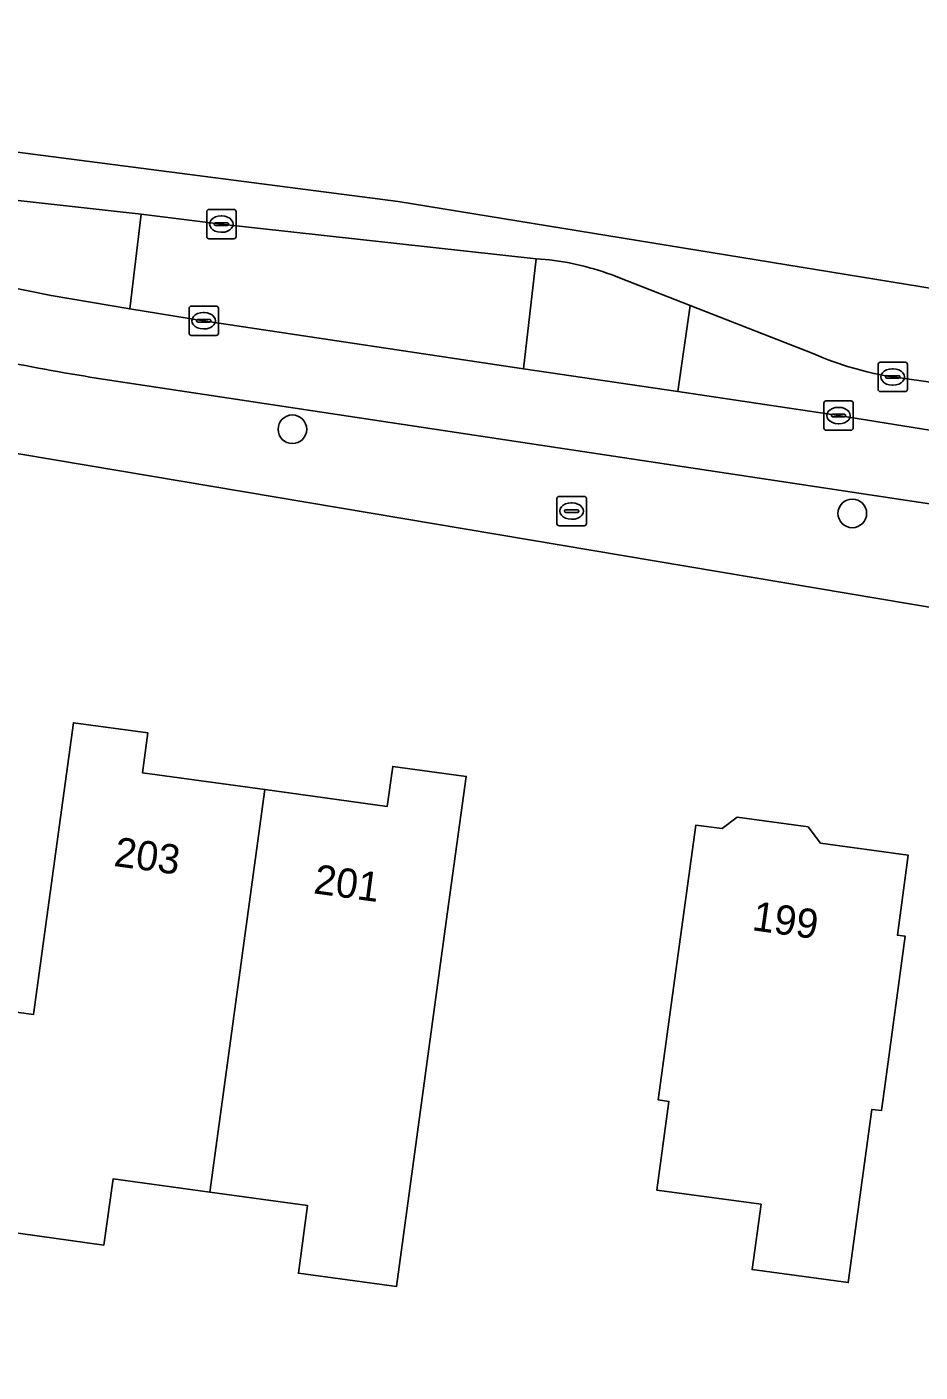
# Model space of a CAD drawing. Extents: x 161483 to 162250, y 379484 to 380833.
# Drawn here: x 161752.71 to 161783.16, y 380783.22 to 380829.09 of the extents above; entities that cross this region are included whole.
import ezdxf

# ---------------------------------------------------------------- set-up
doc = ezdxf.new("R2010")
doc.units = 0
for name, color, linetype in [('IMGEO_Boom', 7, 'Continuous'), ('IMGEO_Brandkraan', 7, 'Continuous'), ('IMGEO_Erf', 7, 'Continuous'), ('IMGEO_Fietspad_gesloten', 7, 'Continuous'), ('IMGEO_Groenvoorziening', 7, 'Continuous'), ('IMGEO_Kolk', 7, 'Continuous'), ('IMGEO_Pand', 7, 'Continuous'), ('IMGEO_Pand_nummerreeks', 7, 'Continuous'), ('IMGEO_Rijbaan_lokaal_gesloten', 7, 'Continuous'), ('IMGEO_Rijbaan_lokaal_open', 7, 'Continuous'), ('IMGEO_Voetpad_open', 7, 'Continuous')]:
    doc.layers.add(name, color=color, linetype=linetype)

msp = doc.modelspace()

# ---------------------------------------------------------------- linework, layer by layer
at = {"layer": 'IMGEO_Boom'}
for centre in [(161761.76, 380815.373), (161780.846, 380812.505)]:
    msp.add_circle(centre, 0.489, dxfattribs=at)
at = {"layer": 'IMGEO_Brandkraan'}
for p, q in [((161770.779, 380812.157), (161770.779, 380813.009)), ((161770.854, 380813.083), (161771.706, 380813.083)), ((161771.267, 380812.863), (161771.292, 380812.863)), ((161771.78, 380813.009), (161771.78, 380812.157)), ((161771.038, 380812.577), (161771.038, 380812.589)), ((161771.476, 380812.54), (161771.078, 380812.54)), ((161771.081, 380812.626), (161771.479, 380812.626)), ((161771.29, 380812.303), (161771.265, 380812.303)), ((161771.522, 380812.589), (161771.522, 380812.577)), ((161771.706, 380812.083), (161770.854, 380812.083))]:
    msp.add_line(p, q, dxfattribs=at)
for points in [[(161770.779, 380812.157), (161770.779, 380813.009)], [(161770.854, 380813.083), (161771.706, 380813.083)], [(161771.78, 380813.009), (161771.78, 380812.157)], [(161771.706, 380812.083), (161770.854, 380812.083)]]:
    msp.add_lwpolyline(points, dxfattribs=at)
for centre, radius, start, end in [((161770.856, 380813.007), 0.0765, 91.552, 178.448), ((161770.856, 380813.007), 0.0765, 91.552, 178.448), ((161771.704, 380813.007), 0.0765, 1.552, 88.448), ((161771.704, 380813.007), 0.0765, 1.552, 88.448), ((161771.078, 380812.586), 0.0403, 85.8775, 175.7526), ((161771.075, 380812.576), 0.0366, 178.938, 274.7102), ((161771.479, 380812.583), 0.043, 264.8664, 352.4533), ((161771.483, 380812.588), 0.0386, 1.7309, 96.639), ((161770.856, 380812.159), 0.0765, 181.552, 268.448), ((161770.856, 380812.159), 0.0765, 181.552, 268.448), ((161771.704, 380812.159), 0.0765, 271.552, 358.448), ((161771.704, 380812.159), 0.0765, 271.552, 358.448)]:
    msp.add_arc(centre, radius, start, end, dxfattribs=at)
for centre, major_axis, ratio, start_param, end_param in [((161771.266, 380812.583), (-0.387, 0.002), 0.722429, 4.712389, 7.853982), ((161771.291, 380812.583), (-0.39, 0.002), 0.717154, 1.570796, 4.712389)]:
    msp.add_ellipse(centre, major_axis=major_axis, ratio=ratio, start_param=start_param, end_param=end_param, dxfattribs=at)
at = {"layer": 'IMGEO_Erf'}
for points in [[(161795.986, 380750), (161798.606, 380766.939), (161796.426, 380767.228), (161792.367, 380767.805), (161790.288, 380768.101), (161791.158, 380774.223), (161797.296, 380773.35), (161802.298, 380806.133), (161751.41, 380814.705)], [(161747.924, 380796.097), (161752.932, 380795.412), (161753.615, 380800.397), (161754.295, 380805.365), (161756.837, 380805.017), (161756.651, 380803.657), (161760.82, 380803.086), (161764.992, 380802.515), (161765.178, 380803.879), (161767.684, 380803.536), (161767.006, 380798.583), (161765.303, 380786.136), (161761.964, 380786.593), (161762.28, 380788.903), (161758.944, 380789.36), (161755.646, 380789.811), (161755.337, 380787.556), (161751.921, 380788.024)]]:
    msp.add_lwpolyline(points, dxfattribs=at)
msp.add_lwpolyline([(161777.431, 380786.721), (161777.735, 380788.944), (161774.182, 380789.43), (161774.596, 380792.453), (161774.233, 380792.503), (161774.836, 380796.91), (161775.516, 380801.878), (161776.408, 380801.756), (161776.923, 380802.147), (161779.34, 380801.816), (161779.765, 380801.256), (161782.754, 380800.847), (161782.381, 380798.122), (161782.652, 380798.085), (161781.974, 380793.132), (161781.838, 380792.138), (161781.513, 380792.182), (161780.705, 380786.273)], close=True, dxfattribs=at)
at = {"layer": 'IMGEO_Fietspad_gesloten'}
for points in [[(161804.365, 380812.235), (161803.183, 380812.392), (161801.708, 380812.617), (161796.502, 380813.413), (161788.76, 380814.556), (161783.559, 380815.336), (161780.373, 380815.84), (161774.902, 380816.657), (161769.635, 380817.438), (161758.733, 380819.073), (161756.214, 380819.476), (161753.535, 380819.931), (161751, 380820.444)], [(161755.294, 380817.086), (161804.583, 380809.653), (161804.89, 380812.158), (161804.95, 380812.65)]]:
    msp.add_lwpolyline(points, dxfattribs=at)
msp.add_arc((161766.089, 380886.748), 70.494, 255.40274, 261.19134, dxfattribs=at)
at = {"layer": 'IMGEO_Groenvoorziening'}
msp.add_lwpolyline([(161770.074, 380821.187), (161759.336, 380822.371), (161756.601, 380822.704), (161756.214, 380819.476), (161758.733, 380819.073), (161769.635, 380817.438)], close=True, dxfattribs=at)
msp.add_lwpolyline([(161779.53, 380817.945), (161775.319, 380819.593), (161774.902, 380816.657), (161780.373, 380815.84), (161783.559, 380815.336), (161783.759, 380816.942), (161782.219, 380817.16)], dxfattribs=at)
msp.add_arc((161783.91, 380827.95), 10.922, 246.358, 261.0938, dxfattribs=at)
at = {"layer": 'IMGEO_Kolk'}
for p, q in [((161758.914, 380822.87), (161759.766, 380822.87)), ((161758.839, 380821.944), (161758.839, 380822.796)), ((161759.141, 380822.413), (161759.539, 380822.413)), ((161759.327, 380822.65), (161759.352, 380822.65)), ((161759.84, 380822.796), (161759.84, 380821.944)), ((161759.098, 380822.364), (161759.098, 380822.376)), ((161759.536, 380822.327), (161759.138, 380822.327)), ((161759.35, 380822.09), (161759.325, 380822.09)), ((161759.582, 380822.376), (161759.582, 380822.364)), ((161759.766, 380821.87), (161758.914, 380821.87)), ((161758.236, 380818.648), (161758.236, 380819.5)), ((161758.311, 380819.574), (161759.163, 380819.574)), ((161758.724, 380819.354), (161758.749, 380819.354)), ((161759.237, 380819.5), (161759.237, 380818.648)), ((161758.495, 380819.068), (161758.495, 380819.08)), ((161758.933, 380819.031), (161758.535, 380819.031)), ((161758.538, 380819.117), (161758.936, 380819.117)), ((161758.747, 380818.794), (161758.722, 380818.794)), ((161758.979, 380819.08), (161758.979, 380819.068)), ((161759.163, 380818.574), (161758.311, 380818.574)), ((161781.722, 380816.732), (161781.722, 380817.584)), ((161781.797, 380817.658), (161782.649, 380817.658)), ((161782.21, 380817.438), (161782.235, 380817.438)), ((161782.723, 380817.584), (161782.723, 380816.732)), ((161781.981, 380817.152), (161781.981, 380817.164)), ((161782.419, 380817.115), (161782.021, 380817.115)), ((161782.024, 380817.201), (161782.422, 380817.201)), ((161782.233, 380816.878), (161782.208, 380816.878)), ((161782.465, 380817.164), (161782.465, 380817.152)), ((161782.649, 380816.658), (161781.797, 380816.658)), ((161779.876, 380815.415), (161779.876, 380816.267)), ((161779.951, 380816.341), (161780.803, 380816.341)), ((161780.364, 380816.121), (161780.389, 380816.121)), ((161780.877, 380816.267), (161780.877, 380815.415)), ((161780.135, 380815.835), (161780.135, 380815.847)), ((161780.573, 380815.798), (161780.175, 380815.798)), ((161780.178, 380815.884), (161780.576, 380815.884)), ((161780.387, 380815.561), (161780.362, 380815.561)), ((161780.619, 380815.847), (161780.619, 380815.835)), ((161780.803, 380815.341), (161779.951, 380815.341))]:
    msp.add_line(p, q, dxfattribs=at)
for points in [[(161758.914, 380822.87), (161759.766, 380822.87)], [(161758.839, 380821.944), (161758.839, 380822.796)], [(161759.84, 380822.796), (161759.84, 380821.944)], [(161759.766, 380821.87), (161758.914, 380821.87)], [(161758.236, 380818.648), (161758.236, 380819.5)], [(161758.311, 380819.574), (161759.163, 380819.574)], [(161759.237, 380819.5), (161759.237, 380818.648)], [(161759.163, 380818.574), (161758.311, 380818.574)], [(161781.722, 380816.732), (161781.722, 380817.584)], [(161781.797, 380817.658), (161782.649, 380817.658)], [(161782.723, 380817.584), (161782.723, 380816.732)], [(161782.649, 380816.658), (161781.797, 380816.658)], [(161779.876, 380815.415), (161779.876, 380816.267)], [(161779.951, 380816.341), (161780.803, 380816.341)], [(161780.877, 380816.267), (161780.877, 380815.415)], [(161780.803, 380815.341), (161779.951, 380815.341)]]:
    msp.add_lwpolyline(points, dxfattribs=at)
for centre, radius, start, end in [((161758.916, 380822.794), 0.0765, 91.552, 178.448), ((161758.916, 380822.794), 0.0765, 91.552, 178.448), ((161759.764, 380822.794), 0.0765, 1.552, 88.448), ((161759.764, 380822.794), 0.0765, 1.552, 88.448), ((161759.138, 380822.373), 0.0403, 85.8775, 175.7526), ((161759.543, 380822.375), 0.0386, 1.7309, 96.639), ((161758.916, 380821.946), 0.0765, 181.552, 268.448), ((161758.916, 380821.946), 0.0765, 181.552, 268.448), ((161759.135, 380822.363), 0.0366, 178.938, 274.7102), ((161759.539, 380822.37), 0.043, 264.8664, 352.4533), ((161759.764, 380821.946), 0.0765, 271.552, 358.448), ((161759.764, 380821.946), 0.0765, 271.552, 358.448), ((161758.313, 380819.498), 0.0765, 91.552, 178.448), ((161758.313, 380819.498), 0.0765, 91.552, 178.448), ((161759.161, 380819.498), 0.0765, 1.552, 88.448), ((161759.161, 380819.498), 0.0765, 1.552, 88.448), ((161758.535, 380819.077), 0.0403, 85.8775, 175.7526), ((161758.532, 380819.067), 0.0366, 178.938, 274.7102), ((161758.936, 380819.074), 0.043, 264.8664, 352.4533), ((161758.94, 380819.079), 0.0386, 1.7309, 96.639), ((161758.313, 380818.65), 0.0765, 181.552, 268.448), ((161758.313, 380818.65), 0.0765, 181.552, 268.448), ((161759.161, 380818.65), 0.0765, 271.552, 358.448), ((161759.161, 380818.65), 0.0765, 271.552, 358.448), ((161781.799, 380817.582), 0.0765, 91.552, 178.448), ((161781.799, 380817.582), 0.0765, 91.552, 178.448), ((161782.647, 380817.582), 0.0765, 1.552, 88.448), ((161782.647, 380817.582), 0.0765, 1.552, 88.448), ((161782.021, 380817.161), 0.0403, 85.8775, 175.7526), ((161782.018, 380817.151), 0.0366, 178.938, 274.7102), ((161782.422, 380817.158), 0.043, 264.8664, 352.4533), ((161782.426, 380817.163), 0.0386, 1.7309, 96.639), ((161781.799, 380816.734), 0.0765, 181.552, 268.448), ((161781.799, 380816.734), 0.0765, 181.552, 268.448), ((161782.647, 380816.734), 0.0765, 271.552, 358.448), ((161782.647, 380816.734), 0.0765, 271.552, 358.448), ((161779.953, 380816.265), 0.0765, 91.552, 178.448), ((161779.953, 380816.265), 0.0765, 91.552, 178.448), ((161780.801, 380816.265), 0.0765, 1.552, 88.448), ((161780.801, 380816.265), 0.0765, 1.552, 88.448), ((161780.175, 380815.844), 0.0403, 85.8775, 175.7526), ((161780.172, 380815.834), 0.0366, 178.938, 274.7102), ((161780.576, 380815.841), 0.043, 264.8664, 352.4533), ((161780.58, 380815.846), 0.0386, 1.7309, 96.639), ((161779.953, 380815.417), 0.0765, 181.552, 268.448), ((161779.953, 380815.417), 0.0765, 181.552, 268.448), ((161780.801, 380815.417), 0.0765, 271.552, 358.448), ((161780.801, 380815.417), 0.0765, 271.552, 358.448)]:
    msp.add_arc(centre, radius, start, end, dxfattribs=at)
for centre, major_axis, ratio, start_param, end_param in [((161759.326, 380822.37), (-0.387, 0.002), 0.722429, 4.712389, 7.853982), ((161759.351, 380822.37), (-0.39, 0.002), 0.717154, 1.570796, 4.712389), ((161758.723, 380819.074), (-0.387, 0.002), 0.722429, 4.712389, 7.853982), ((161758.748, 380819.074), (-0.39, 0.002), 0.717154, 1.570796, 4.712389), ((161782.209, 380817.158), (-0.387, 0.002), 0.722429, 4.712389, 7.853982), ((161782.234, 380817.158), (-0.39, 0.002), 0.717154, 1.570796, 4.712389), ((161780.363, 380815.841), (-0.387, 0.002), 0.722429, 4.712389, 7.853982), ((161780.388, 380815.841), (-0.39, 0.002), 0.717154, 1.570796, 4.712389)]:
    msp.add_ellipse(centre, major_axis=major_axis, ratio=ratio, start_param=start_param, end_param=end_param, dxfattribs=at)
at = {"layer": 'IMGEO_Pand'}
for points in [[(161760.82, 380803.086), (161756.651, 380803.657), (161756.837, 380805.017), (161754.295, 380805.365), (161753.615, 380800.397), (161752.932, 380795.412), (161747.924, 380796.097), (161747.445, 380792.911), (161746.871, 380788.716), (161751.921, 380788.024), (161755.337, 380787.556), (161755.646, 380789.811), (161758.944, 380789.36)], [(161758.944, 380789.36), (161762.28, 380788.903), (161761.964, 380786.593), (161765.303, 380786.136), (161767.006, 380798.583), (161767.684, 380803.536), (161765.178, 380803.879), (161764.992, 380802.515), (161760.82, 380803.086)], [(161774.836, 380796.91), (161774.233, 380792.503), (161774.596, 380792.453), (161774.182, 380789.43), (161777.735, 380788.944), (161777.431, 380786.721), (161780.705, 380786.273), (161781.513, 380792.182), (161781.838, 380792.138), (161781.974, 380793.132), (161782.652, 380798.085), (161782.381, 380798.122), (161782.754, 380800.847), (161779.765, 380801.256), (161779.34, 380801.816), (161776.923, 380802.147), (161776.408, 380801.756), (161775.516, 380801.878)]]:
    msp.add_lwpolyline(points, close=True, dxfattribs=at)
at = {"layer": 'IMGEO_Rijbaan_lokaal_gesloten'}
for points in [[(162235.883, 380761.117), (162225.793, 380762.232), (162195.841, 380761.556), (162155.522, 380766.113), (162152.312, 380766.476), (162100.246, 380775.712), (162094.38, 380775.785), (162063.3, 380779.137), (162022.247, 380782.773), (161914.65, 380797.204), (161859.959, 380804.218), (161826.791, 380811.355), (161807.579, 380816.265), (161765.369, 380823.138), (161719.379, 380829.094), (161719.203, 380827.684), (161722.585, 380827.174), (161725.837, 380826.617)], [(161740.936, 380824.357), (161751.38, 380823.286), (161756.601, 380822.704), (161759.336, 380822.371), (161770.074, 380821.187), (161770.528, 380821.15)], [(161772.915, 380820.535), (161775.319, 380819.593), (161779.53, 380817.945)], [(161782.219, 380817.16), (161783.759, 380816.942), (161788.984, 380816.146), (161796.729, 380814.966), (161801.914, 380814.196), (161803.411, 380813.985)]]:
    msp.add_lwpolyline(points, dxfattribs=at)
for centre, radius, start, end in [((161769.424, 380811.924), 9.292, 67.93, 83.1744), ((161783.91, 380827.95), 10.922, 246.358, 261.0938)]:
    msp.add_arc(centre, radius, start, end, dxfattribs=at)
at = {"layer": 'IMGEO_Rijbaan_lokaal_open'}
msp.add_lwpolyline([(161756.601, 380822.704), (161751.38, 380823.286), (161751, 380820.444), (161753.535, 380819.931), (161756.214, 380819.476)], close=True, dxfattribs=at)
for points in [[(161770.528, 380821.15), (161770.074, 380821.187), (161769.635, 380817.438), (161774.902, 380816.657), (161775.319, 380819.593)], [(161775.319, 380819.593), (161772.915, 380820.535)]]:
    msp.add_lwpolyline(points, dxfattribs=at)
msp.add_arc((161769.424, 380811.924), 9.292, 67.93, 83.1744, dxfattribs=at)
at = {"layer": 'IMGEO_Voetpad_open'}
for points in [[(161710.094, 380821.009), (161711.799, 380820.724), (161733.616, 380817.357), (161747.488, 380815.262), (161751.41, 380814.705), (161802.298, 380806.133), (161807.605, 380805.299)], [(161805.523, 380809.521), (161804.583, 380809.653), (161755.294, 380817.086)]]:
    msp.add_lwpolyline(points, dxfattribs=at)
msp.add_arc((161766.089, 380886.748), 70.494, 255.40274, 261.19134, dxfattribs=at)

# ---------------------------------------------------------------- texts
at = {"layer": 'IMGEO_Pand_nummerreeks'}
for s, rotation, p in [('203', 352.202, (161755.645, 380800.485)), ('201', 352.2039, (161762.452, 380799.552)), ('199', 351.8932, (161777.398, 380798.297))]:
    msp.add_text(s, height=1, rotation=rotation, dxfattribs=at).set_placement(p)

doc.saveas('drawing.dxf')
